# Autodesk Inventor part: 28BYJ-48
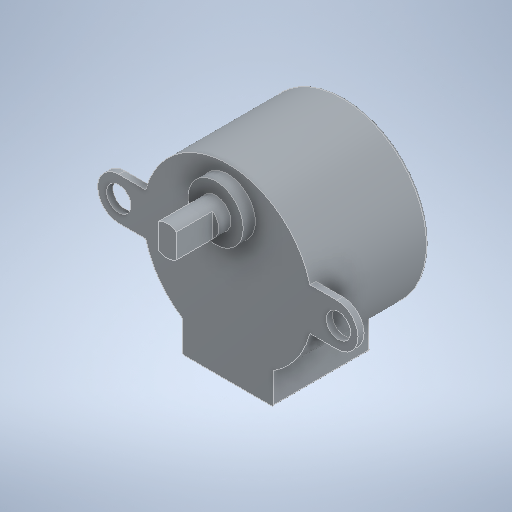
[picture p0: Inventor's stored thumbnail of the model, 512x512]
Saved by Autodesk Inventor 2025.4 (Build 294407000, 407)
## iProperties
Created: 2026-05
Part Number: 28BYJ-48
Material: Generic
Description: FreeCAD Model
Document SubType Name: Modeling
Designer: Marcio Valenzuela
Authority: Unknown
Density: 1 g/cm^3
Appearance: Default
Sending System: FreeCAD
Preprocessor: Open CASCADE STEP processor 7.8
Title: Open CASCADE Shape Model
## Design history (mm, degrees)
feature "Base1"
body "Solid1"
